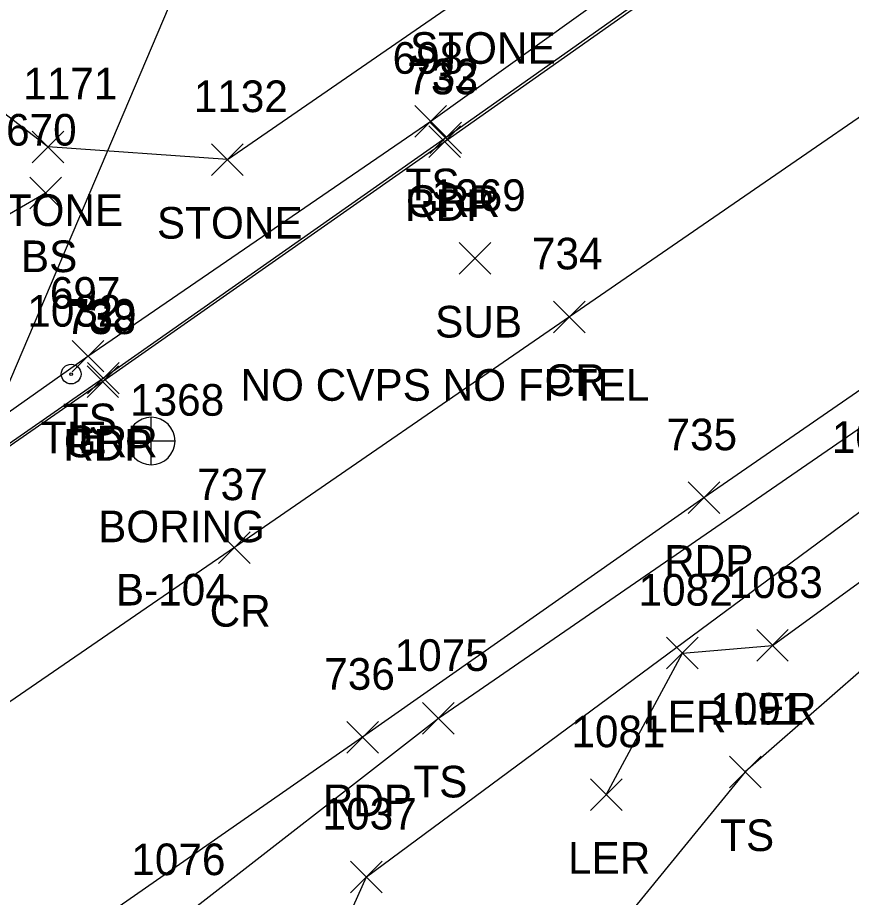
# Model space of a CAD drawing. Extents: x 1528286 to 1556263, y 492387 to 508952.
# Drawn here: x 1528684.2 to 1528736.9, y 492794 to 492849.7 of the extents above; entities that cross this region are included whole.
import ezdxf

# ---------------------------------------------------------------- set-up
doc = ezdxf.new("R2010")
doc.units = 0
for name, color, linetype in [('C_A', 7, 'Continuous'), ('C_I', 7, 'Continuous'), ('CBP', 7, 'Continuous'), ('DCP', 7, 'Continuous'), ('G_A', 7, 'Continuous'), ('G_C', 7, 'Continuous'), ('G_I', 7, 'Continuous'), ('GA_P', 7, 'Continuous'), ('L_A', 7, 'Continuous'), ('L_I', 7, 'Continuous'), ('L_TIC', 7, 'Continuous'), ('LARO', 7, 'Continuous'), ('LASF', 7, 'Continuous'), ('LELB', 7, 'Continuous'), ('P_A', 7, 'Continuous'), ('P_I', 7, 'Continuous'), ('P_TIC', 7, 'Continuous'), ('PET', 7, 'Continuous'), ('PRC', 7, 'Continuous'), ('R_A', 7, 'Continuous'), ('R_I', 7, 'Continuous'), ('R_TIC', 7, 'Continuous'), ('RGR', 7, 'Continuous'), ('U_A', 7, 'Continuous'), ('U_C', 7, 'Continuous'), ('U_I', 7, 'Continuous'), ('U_TIC', 7, 'Continuous')]:
    doc.layers.add(name, color=color, linetype=linetype)

msp = doc.modelspace()

# ---------------------------------------------------------------- linework, layer by layer
at = {"layer": 'CBP'}
for radius in [0.625, 0.625, 0.0833, 0.0833]:
    msp.add_circle((1528687.554, 492827.127), radius, dxfattribs=at)
at = {"layer": 'DCP'}
msp.add_lwpolyline([(1528644.198, 492733.843), (1528697.661, 492859.59)], dxfattribs=at)
msp.add_lwpolyline([(1528644.198, 492733.843), (1528697.661, 492859.59)], dxfattribs=at)
at = {"layer": 'GA_P'}
for p, q in [((1528692.622, 492822.896), (1528692.622, 492824.396)), ((1528692.622, 492822.896), (1528692.622, 492824.396)), ((1528692.622, 492822.896), (1528691.122, 492822.896)), ((1528692.622, 492822.896), (1528691.122, 492822.896)), ((1528694.122, 492822.896), (1528692.622, 492822.896)), ((1528692.622, 492821.396), (1528692.622, 492822.896)), ((1528694.122, 492822.896), (1528692.622, 492822.896)), ((1528692.622, 492821.396), (1528692.622, 492822.896))]:
    msp.add_line(p, q, dxfattribs=at)
for start, end in [(90, 180), (90, 180), (0, 90), (0, 90), (180, 270), (180, 270), (270, 0), (270, 0)]:
    msp.add_arc((1528692.622, 492822.896), 1.5, start, end, dxfattribs=at)
at = {"layer": 'L_TIC'}
for points in [[(1528709.289, 492842.118), (1528711.289, 492844.118)], [(1528711.289, 492842.118), (1528709.289, 492844.118)], [(1528709.289, 492842.118), (1528711.289, 492844.118)], [(1528711.289, 492842.118), (1528709.289, 492844.118)], [(1528685.086, 492840.492), (1528687.086, 492842.492)], [(1528687.086, 492840.492), (1528685.086, 492842.492)], [(1528685.086, 492840.492), (1528687.086, 492842.492)], [(1528687.086, 492840.492), (1528685.086, 492842.492)], [(1528696.435, 492839.692), (1528698.435, 492841.692)], [(1528698.435, 492839.692), (1528696.435, 492841.692)], [(1528696.435, 492839.692), (1528698.435, 492841.692)], [(1528698.435, 492839.692), (1528696.435, 492841.692)], [(1528696.435, 492839.692), (1528698.435, 492841.692)], [(1528698.435, 492839.692), (1528696.435, 492841.692)], [(1528696.435, 492839.692), (1528698.435, 492841.692)], [(1528698.435, 492839.692), (1528696.435, 492841.692)], [(1528684.936, 492837.575), (1528686.936, 492839.575)], [(1528686.936, 492837.575), (1528684.936, 492839.575)], [(1528684.936, 492837.575), (1528686.936, 492839.575)], [(1528686.936, 492837.575), (1528684.936, 492839.575)], [(1528687.619, 492827.262), (1528689.619, 492829.262)], [(1528689.619, 492827.262), (1528687.619, 492829.262)], [(1528687.619, 492827.262), (1528689.619, 492829.262)], [(1528689.619, 492827.262), (1528687.619, 492829.262)], [(1528730.901, 492808.971), (1528732.901, 492810.971)], [(1528732.901, 492808.971), (1528730.901, 492810.971)], [(1528730.901, 492808.971), (1528732.901, 492810.971)], [(1528732.901, 492808.971), (1528730.901, 492810.971)], [(1528725.203, 492808.487), (1528727.203, 492810.487)], [(1528727.203, 492808.487), (1528725.203, 492810.487)], [(1528725.203, 492808.487), (1528727.203, 492810.487)], [(1528727.203, 492808.487), (1528725.203, 492810.487)], [(1528709.78, 492804.361), (1528711.78, 492806.361)], [(1528711.78, 492804.361), (1528709.78, 492806.361)], [(1528709.78, 492804.361), (1528711.78, 492806.361)], [(1528711.78, 492804.361), (1528709.78, 492806.361)], [(1528729.179, 492800.971), (1528731.179, 492802.971)], [(1528731.179, 492800.971), (1528729.179, 492802.971)], [(1528729.179, 492800.971), (1528731.179, 492802.971)], [(1528731.179, 492800.971), (1528729.179, 492802.971)], [(1528720.391, 492799.536), (1528722.391, 492801.536)], [(1528722.391, 492799.536), (1528720.391, 492801.536)], [(1528720.391, 492799.536), (1528722.391, 492801.536)], [(1528722.391, 492799.536), (1528720.391, 492801.536)], [(1528705.225, 492794.334), (1528707.225, 492796.334)], [(1528707.225, 492794.334), (1528705.225, 492796.334)], [(1528705.225, 492794.334), (1528707.225, 492796.334)], [(1528707.225, 492794.334), (1528705.225, 492796.334)]]:
    msp.add_lwpolyline(points, dxfattribs=at)
at = {"layer": 'LARO'}
msp.add_lwpolyline([(1528721.391, 492800.536), (1528726.203, 492809.487), (1528731.901, 492809.971), (1528750.707, 492823.643), (1528765.205, 492834.16), (1528770.059, 492839.482), (1528771.069, 492833.555)], dxfattribs=at)
msp.add_lwpolyline([(1528721.391, 492800.536), (1528726.203, 492809.487), (1528731.901, 492809.971), (1528750.707, 492823.643), (1528765.205, 492834.16), (1528770.059, 492839.482), (1528771.069, 492833.555)], dxfattribs=at)
at = {"layer": 'LASF'}
for points in [[(1528697.435, 492840.692), (1528713.436, 492851.745), (1528713.016, 492874.791), (1528707.447, 492872.268), (1528700.556, 492858.291)], [(1528697.435, 492840.692), (1528713.436, 492851.745), (1528713.016, 492874.791), (1528707.447, 492872.268), (1528700.556, 492858.291)], [(1528686.086, 492841.492), (1528678.095, 492847.611)], [(1528686.086, 492841.492), (1528678.095, 492847.611)], [(1528697.435, 492840.692), (1528686.086, 492841.492)], [(1528697.435, 492840.692), (1528686.086, 492841.492)]]:
    msp.add_lwpolyline(points, dxfattribs=at)
at = {"layer": 'LELB'}
for points in [[(1528511.531, 492702.846), (1528534.14, 492721.314), (1528572.642, 492751.164), (1528586.729, 492763.586), (1528600.497, 492766.346), (1528613.458, 492775.516), (1528652.2, 492802.526), (1528688.619, 492828.262), (1528710.289, 492843.118), (1528742.907, 492866.471), (1528778.713, 492891.266), (1528817.445, 492919.082), (1528857.746, 492946.937), (1528897.372, 492973.983), (1528940.286, 493003.739)], [(1528511.531, 492702.846), (1528534.14, 492721.314), (1528572.642, 492751.164), (1528586.729, 492763.586), (1528600.497, 492766.346), (1528613.458, 492775.516), (1528652.2, 492802.526), (1528688.619, 492828.262), (1528710.289, 492843.118), (1528742.907, 492866.471), (1528778.713, 492891.266), (1528817.445, 492919.082), (1528857.746, 492946.937), (1528897.372, 492973.983), (1528940.286, 493003.739)], [(1528946.969, 492932.586), (1528919.959, 492926.163), (1528896.398, 492920.638), (1528892.931, 492919.077), (1528869.957, 492910.976), (1528843.058, 492896.384), (1528834.233, 492890.275), (1528806.992, 492871.856), (1528782.492, 492854.983), (1528750.989, 492833.046), (1528710.78, 492805.361), (1528694.188, 492792.448), (1528682.217, 492773.575), (1528672.784, 492775.788)], [(1528946.969, 492932.586), (1528919.959, 492926.163), (1528896.398, 492920.638), (1528892.931, 492919.077), (1528869.957, 492910.976), (1528843.058, 492896.384), (1528834.233, 492890.275), (1528806.992, 492871.856), (1528782.492, 492854.983), (1528750.989, 492833.046), (1528710.78, 492805.361), (1528694.188, 492792.448), (1528682.217, 492773.575), (1528672.784, 492775.788)], [(1528675.196, 492746.898), (1528689.3, 492770.432), (1528699.745, 492780.853), (1528706.225, 492795.334), (1528738.423, 492819.149), (1528757.61, 492832.596), (1528783.379, 492849.877), (1528832.015, 492885.927)], [(1528675.196, 492746.898), (1528689.3, 492770.432), (1528699.745, 492780.853), (1528706.225, 492795.334), (1528738.423, 492819.149), (1528757.61, 492832.596), (1528783.379, 492849.877), (1528832.015, 492885.927)], [(1528685.936, 492838.575), (1528672.607, 492830.811), (1528666.617, 492820.24), (1528643.207, 492802.995), (1528614.904, 492783.769), (1528590.503, 492768.834), (1528580.049, 492763.591), (1528573.986, 492757.651), (1528555.822, 492743.679), (1528531.303, 492723.898), (1528516.93, 492710.506), (1528511.372, 492706.597)], [(1528685.936, 492838.575), (1528672.607, 492830.811), (1528666.617, 492820.24), (1528643.207, 492802.995), (1528614.904, 492783.769), (1528590.503, 492768.834), (1528580.049, 492763.591), (1528573.986, 492757.651), (1528555.822, 492743.679), (1528531.303, 492723.898), (1528516.93, 492710.506), (1528511.372, 492706.597)], [(1528771.365, 492833.538), (1528753.465, 492821.029), (1528741.176, 492811.597), (1528730.179, 492801.971), (1528717.825, 492786.839)], [(1528771.365, 492833.538), (1528753.465, 492821.029), (1528741.176, 492811.597), (1528730.179, 492801.971), (1528717.825, 492786.839)]]:
    msp.add_lwpolyline(points, dxfattribs=at)
at = {"layer": 'P_TIC'}
for points in [[(1528710.173, 492840.816), (1528712.173, 492842.816)], [(1528712.173, 492840.816), (1528710.173, 492842.816)], [(1528710.173, 492840.816), (1528712.173, 492842.816)], [(1528712.173, 492840.816), (1528710.173, 492842.816)], [(1528718.055, 492829.747), (1528720.055, 492831.747)], [(1528720.055, 492829.747), (1528718.055, 492831.747)], [(1528718.055, 492829.747), (1528720.055, 492831.747)], [(1528720.055, 492829.747), (1528718.055, 492831.747)], [(1528688.558, 492825.658), (1528690.558, 492827.658)], [(1528690.558, 492825.658), (1528688.558, 492827.658)], [(1528688.558, 492825.658), (1528690.558, 492827.658)], [(1528690.558, 492825.658), (1528688.558, 492827.658)], [(1528726.561, 492818.312), (1528728.561, 492820.312)], [(1528728.561, 492818.312), (1528726.561, 492820.312)], [(1528726.561, 492818.312), (1528728.561, 492820.312)], [(1528728.561, 492818.312), (1528726.561, 492820.312)], [(1528696.879, 492815.158), (1528698.879, 492817.158)], [(1528698.879, 492815.158), (1528696.879, 492817.158)], [(1528696.879, 492815.158), (1528698.879, 492817.158)], [(1528698.879, 492815.158), (1528696.879, 492817.158)], [(1528704.978, 492803.168), (1528706.978, 492805.168)], [(1528706.978, 492803.168), (1528704.978, 492805.168)], [(1528704.978, 492803.168), (1528706.978, 492805.168)], [(1528706.978, 492803.168), (1528704.978, 492805.168)]]:
    msp.add_lwpolyline(points, dxfattribs=at)
at = {"layer": 'PET'}
for points in [[(1528941.998, 493002.12), (1528898.48, 492972.509), (1528859.279, 492945.341), (1528819.079, 492917.533), (1528787.553, 492894.483), (1528780.465, 492889.936), (1528744.229, 492865.118), (1528711.173, 492841.816), (1528689.558, 492826.658), (1528653.332, 492801.515)], [(1528941.998, 493002.12), (1528898.48, 492972.509), (1528859.279, 492945.341), (1528819.079, 492917.533), (1528787.553, 492894.483), (1528780.465, 492889.936), (1528744.229, 492865.118), (1528711.173, 492841.816), (1528689.558, 492826.658), (1528653.332, 492801.515)], [(1528796.008, 492866.532), (1528760.738, 492842.185), (1528727.561, 492819.312), (1528705.978, 492804.168), (1528668.887, 492778.385)], [(1528796.008, 492866.532), (1528760.738, 492842.185), (1528727.561, 492819.312), (1528705.978, 492804.168), (1528668.887, 492778.385)]]:
    msp.add_lwpolyline(points, dxfattribs=at)
at = {"layer": 'PRC'}
msp.add_lwpolyline([(1528788.693, 492878.598), (1528752.937, 492854.076), (1528719.055, 492830.747), (1528697.879, 492816.158), (1528660.714, 492790.64)], dxfattribs=at)
msp.add_lwpolyline([(1528788.693, 492878.598), (1528752.937, 492854.076), (1528719.055, 492830.747), (1528697.879, 492816.158), (1528660.714, 492790.64)], dxfattribs=at)
at = {"layer": 'R_TIC'}
for points in [[(1528710.237, 492841.066), (1528712.237, 492843.066)], [(1528712.237, 492841.066), (1528710.237, 492843.066)], [(1528710.237, 492841.066), (1528712.237, 492843.066)], [(1528712.237, 492841.066), (1528710.237, 492843.066)], [(1528688.599, 492825.87), (1528690.599, 492827.87)], [(1528690.599, 492825.87), (1528688.599, 492827.87)], [(1528688.599, 492825.87), (1528690.599, 492827.87)], [(1528690.599, 492825.87), (1528688.599, 492827.87)]]:
    msp.add_lwpolyline(points, dxfattribs=at)
at = {"layer": 'RGR'}
msp.add_lwpolyline([(1528941.405, 493002.785), (1528898.116, 492973.218), (1528858.975, 492945.897), (1528818.829, 492918.12), (1528780.054, 492890.637), (1528744.146, 492865.314), (1528711.237, 492842.066), (1528689.599, 492826.87), (1528653.301, 492801.623)], dxfattribs=at)
msp.add_lwpolyline([(1528941.405, 493002.785), (1528898.116, 492973.218), (1528858.975, 492945.897), (1528818.829, 492918.12), (1528780.054, 492890.637), (1528744.146, 492865.314), (1528711.237, 492842.066), (1528689.599, 492826.87), (1528653.301, 492801.623)], dxfattribs=at)
at = {"layer": 'U_TIC'}
for points in [[(1528712.096, 492833.441), (1528714.096, 492835.441)], [(1528714.096, 492833.441), (1528712.096, 492835.441)], [(1528712.096, 492833.441), (1528714.096, 492835.441)], [(1528714.096, 492833.441), (1528712.096, 492835.441)]]:
    msp.add_lwpolyline(points, dxfattribs=at)

# ---------------------------------------------------------------- texts
at = {"layer": 'C_A'}
msp.add_text('TIE', height=2, dxfattribs=at).set_placement((1528685.633, 492822.127))
msp.add_text('TIE', height=2, dxfattribs=at).set_placement((1528685.633, 492822.127))
at = {"layer": 'C_I'}
msp.add_text('1032', height=2, dxfattribs=at).set_placement((1528684.783, 492830.127))
msp.add_text('1032', height=2, dxfattribs=at).set_placement((1528684.783, 492830.127))
at = {"layer": 'G_A'}
msp.add_text('BORING', height=2, dxfattribs=at).set_placement((1528689.259, 492816.496))
msp.add_text('BORING', height=2, dxfattribs=at).set_placement((1528689.259, 492816.496))
at = {"layer": 'G_C'}
msp.add_text('B-104', height=2, dxfattribs=at).set_placement((1528690.385, 492812.496))
msp.add_text('B-104', height=2, dxfattribs=at).set_placement((1528690.385, 492812.496))
at = {"layer": 'G_I'}
msp.add_text('1368', height=2, dxfattribs=at).set_placement((1528691.282, 492824.496))
msp.add_text('1368', height=2, dxfattribs=at).set_placement((1528691.282, 492824.496))
at = {"layer": 'L_A'}
for s, p in [('STONE', (1528708.98, 492846.745)), ('STONE', (1528708.98, 492846.745)), ('TS', (1528708.698, 492838.118)), ('TS', (1528708.698, 492838.118)), ('STONE', (1528681.629, 492836.492)), ('STONE', (1528681.629, 492836.492)), ('STONE', (1528692.978, 492835.692)), ('STONE', (1528692.978, 492835.692)), ('STONE', (1528692.978, 492835.692)), ('STONE', (1528692.978, 492835.692)), ('BS', (1528684.377, 492833.575)), ('BS', (1528684.377, 492833.575)), ('TS', (1528687.028, 492823.262)), ('TS', (1528687.028, 492823.262)), ('LER', (1528729.484, 492804.971)), ('LER', (1528729.484, 492804.971)), ('LER', (1528723.786, 492804.487)), ('LER', (1528723.786, 492804.487)), ('TS', (1528709.19, 492800.361)), ('TS', (1528709.19, 492800.361)), ('TS', (1528728.588, 492796.971)), ('TS', (1528728.588, 492796.971)), ('LER', (1528718.973, 492795.536)), ('LER', (1528718.973, 492795.536))]:
    msp.add_text(s, height=2, dxfattribs=at).set_placement(p)
at = {"layer": 'L_I'}
for s, p in [('698', (1528707.879, 492846.118)), ('698', (1528707.879, 492846.118)), ('1171', (1528684.527, 492844.492)), ('1171', (1528684.527, 492844.492)), ('1132', (1528695.309, 492843.692)), ('1132', (1528695.309, 492843.692)), ('1132', (1528695.309, 492843.692)), ('1132', (1528695.309, 492843.692)), ('670', (1528683.44, 492841.575)), ('670', (1528683.44, 492841.575)), ('697', (1528686.209, 492831.262)), ('697', (1528686.209, 492831.262)), ('1038', (1528735.651, 492822.149)), ('1038', (1528735.651, 492822.149)), ('1082', (1528723.432, 492812.487)), ('1082', (1528723.432, 492812.487)), ('1083', (1528729.129, 492812.971)), ('1083', (1528729.129, 492812.971)), ('1075', (1528708.009, 492808.361)), ('1075', (1528708.009, 492808.361)), ('1091', (1528727.974, 492804.971)), ('1091', (1528727.974, 492804.971)), ('1081', (1528719.186, 492803.536)), ('1081', (1528719.186, 492803.536)), ('1037', (1528703.453, 492798.334)), ('1037', (1528703.453, 492798.334)), ('1076', (1528691.362, 492795.448)), ('1076', (1528691.362, 492795.448))]:
    msp.add_text(s, height=2, dxfattribs=at).set_placement(p)
at = {"layer": 'P_A'}
for s, p in [('RDP', (1528708.661, 492836.816)), ('RDP', (1528708.661, 492836.816)), ('CR', (1528717.488, 492825.747)), ('CR', (1528717.488, 492825.747)), ('RDP', (1528687.046, 492821.658)), ('RDP', (1528687.046, 492821.658)), ('RDP', (1528725.049, 492814.312)), ('RDP', (1528725.049, 492814.312)), ('CR', (1528696.312, 492811.158)), ('CR', (1528696.312, 492811.158)), ('RDP', (1528703.467, 492799.168)), ('RDP', (1528703.467, 492799.168))]:
    msp.add_text(s, height=2, dxfattribs=at).set_placement(p)
at = {"layer": 'P_I'}
for s, p in [('733', (1528708.81, 492844.816)), ('733', (1528708.81, 492844.816)), ('734', (1528716.693, 492833.747)), ('734', (1528716.693, 492833.747)), ('738', (1528687.196, 492829.658)), ('738', (1528687.196, 492829.658)), ('735', (1528725.199, 492822.312)), ('735', (1528725.199, 492822.312)), ('737', (1528695.517, 492819.158)), ('737', (1528695.517, 492819.158)), ('736', (1528703.561, 492807.168)), ('736', (1528703.561, 492807.168))]:
    msp.add_text(s, height=2, dxfattribs=at).set_placement(p)
at = {"layer": 'R_A'}
for p in [(1528708.725, 492837.066), (1528708.725, 492837.066), (1528687.087, 492821.87), (1528687.087, 492821.87)]:
    msp.add_text('GRR', height=2, dxfattribs=at).set_placement(p)
at = {"layer": 'R_I'}
for s, p in [('732', (1528708.874, 492845.066)), ('732', (1528708.874, 492845.066)), ('739', (1528687.229, 492829.87)), ('739', (1528687.229, 492829.87))]:
    msp.add_text(s, height=2, dxfattribs=at).set_placement(p)
at = {"layer": 'U_A'}
msp.add_text('SUB', height=2, dxfattribs=at).set_placement((1528710.568, 492829.441))
msp.add_text('SUB', height=2, dxfattribs=at).set_placement((1528710.568, 492829.441))
at = {"layer": 'U_C'}
msp.add_text('NO CVPS NO FPTEL', height=2, dxfattribs=at).set_placement((1528698.261, 492825.441))
msp.add_text('NO CVPS NO FPTEL', height=2, dxfattribs=at).set_placement((1528698.261, 492825.441))
at = {"layer": 'U_I'}
msp.add_text('1369', height=2, dxfattribs=at).set_placement((1528710.348, 492837.441))
msp.add_text('1369', height=2, dxfattribs=at).set_placement((1528710.348, 492837.441))

doc.saveas('drawing.dxf')
